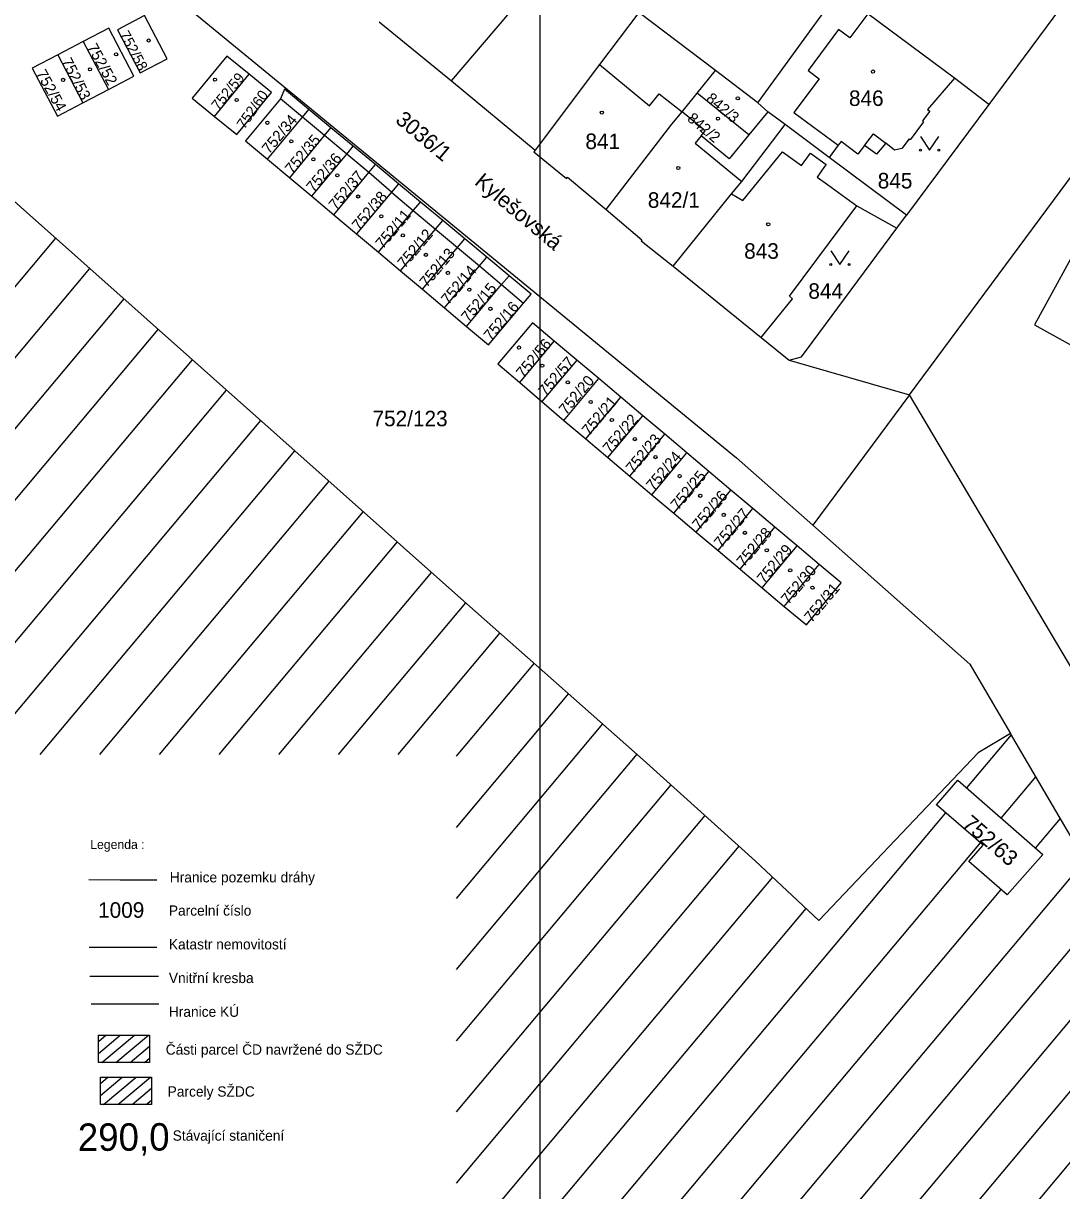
# Model space of a CAD drawing. Extents: x -496682 to -495776, y -1088797 to -1088018.
# Drawn here: x -496193.9 to -496080.3, y -1088434.2 to -1088306.6 of the extents above; entities that cross this region are included whole.
import ezdxf

# ---------------------------------------------------------------- set-up
doc = ezdxf.new("R2010")
doc.units = 0
for name, color, linetype in [('Hranice parcel', 7, 'Continuous'), ('LEGENDA', 7, 'Continuous'), ('Parcelní čísla', 7, 'Continuous'), ('Pop  PČ popisy', 7, 'Continuous'), ('Vnitřní kresba', 7, 'Continuous'), ('Vrstva 20', 7, 'Continuous'), ('Vrstva 63', 7, 'Continuous'), ('Značky budov', 7, 'Continuous'), ('Značky kultur', 7, 'Continuous')]:
    doc.layers.add(name, color=color, linetype=linetype)

msp = doc.modelspace()

# ---------------------------------------------------------------- linework, layer by layer
at = {"layer": 'Hranice parcel'}
for p, q in [((-496113.5, -1088315.25), (-496104.68, -1088303.11)), ((-496079.66, -1088303.84), (-496088.23, -1088315.43)), ((-496118.15, -1088311.73), (-496126.53, -1088305.37)), ((-496154.95, -1088306.41), (-496147.01, -1088312.86)), ((-496187.32, -1088308.54), (-496190.11, -1088310)), ((-496187.32, -1088308.54), (-496184.56, -1088313.8)), ((-496190.11, -1088310), (-496187.36, -1088315.26)), ((-496172.94, -1088316.74), (-496169.17, -1088312.12)), ((-496120.16, -1088314.21), (-496118.15, -1088311.73)), ((-496113.5, -1088315.25), (-496118.15, -1088311.73)), ((-496088.23, -1088315.43), (-496092.02, -1088312.57)), ((-496187.36, -1088315.26), (-496184.56, -1088313.8)), ((-496147.01, -1088312.86), (-496137.88, -1088320.43)), ((-496121.81, -1088316.24), (-496120.16, -1088314.21)), ((-496114.51, -1088318.76), (-496120.16, -1088314.21)), ((-496160.21, -1088317.99), (-496162.63, -1088315.98)), ((-496112.44, -1088316.23), (-496114.51, -1088318.76)), ((-496112.44, -1088316.23), (-496113.5, -1088315.25)), ((-496110.54, -1088317.61), (-496112.44, -1088316.23)), ((-496088.23, -1088315.43), (-496097.26, -1088327.56)), ((-496105.72, -1088321.22), (-496110.54, -1088317.61)), ((-496157.78, -1088320.01), (-496160.21, -1088317.99)), ((-496096.94, -1088347.2), (-496075.94, -1088318.85)), ((-496155.35, -1088322.02), (-496157.78, -1088320.01)), ((-496167.15, -1088321.43), (-496164.73, -1088323.45)), ((-496097.26, -1088327.56), (-496105.72, -1088321.22)), ((-496152.84, -1088324.11), (-496155.35, -1088322.02)), ((-496164.73, -1088323.45), (-496162.32, -1088325.48)), ((-496150.42, -1088326.11), (-496152.84, -1088324.11)), ((-496122.78, -1088333.12), (-496116.38, -1088325.22)), ((-496162.32, -1088325.48), (-496159.9, -1088327.5)), ((-496147.99, -1088328.13), (-496150.42, -1088326.11)), ((-496159.9, -1088327.5), (-496157.42, -1088329.57)), ((-496098.3, -1088328.96), (-496097.26, -1088327.56)), ((-496145.58, -1088330.13), (-496147.99, -1088328.13)), ((-496157.42, -1088329.57), (-496155.02, -1088331.59)), ((-496143.15, -1088332.15), (-496145.58, -1088330.13)), ((-496155.02, -1088331.59), (-496152.6, -1088333.64)), ((-496140.72, -1088334.17), (-496143.15, -1088332.15)), ((-496123.28, -1088332.72), (-496122.78, -1088333.12)), ((-496152.6, -1088333.64), (-496150.21, -1088335.65)), ((-496122.78, -1088333.12), (-496113.14, -1088340.92)), ((-496150.21, -1088335.65), (-496147.79, -1088337.68)), ((-496147.79, -1088337.68), (-496145.37, -1088339.71)), ((-496139.57, -1088345.84), (-496135.78, -1088341.33)), ((-496133.31, -1088343.39), (-496135.78, -1088341.33)), ((-496113.14, -1088340.92), (-496110.08, -1088343.39)), ((-496133.31, -1088343.39), (-496137.13, -1088347.93)), ((-496130.91, -1088345.41), (-496133.31, -1088343.39)), ((-496110.08, -1088343.39), (-496096.94, -1088347.2)), ((-496134.74, -1088349.98), (-496130.91, -1088345.41)), ((-496128.5, -1088347.44), (-496130.91, -1088345.41)), ((-496139.57, -1088345.84), (-496137.13, -1088347.93)), ((-496137.13, -1088347.93), (-496134.74, -1088349.98)), ((-496132.33, -1088352.01), (-496128.5, -1088347.44)), ((-496126.09, -1088349.48), (-496128.5, -1088347.44)), ((-496096.94, -1088347.2), (-496107.5, -1088361.45)), ((-496078.26, -1088378.65), (-496096.94, -1088347.2)), ((-496129.94, -1088354.04), (-496126.09, -1088349.48)), ((-496123.68, -1088351.51), (-496126.09, -1088349.48)), ((-496134.74, -1088349.98), (-496132.33, -1088352.01)), ((-496132.33, -1088352.01), (-496129.94, -1088354.04)), ((-496127.52, -1088356.07), (-496123.68, -1088351.51)), ((-496121.27, -1088353.54), (-496123.68, -1088351.51)), ((-496129.94, -1088354.04), (-496127.52, -1088356.07)), ((-496125.1, -1088358.11), (-496121.27, -1088353.54)), ((-496118.87, -1088355.57), (-496121.27, -1088353.54)), ((-496122.69, -1088360.15), (-496118.87, -1088355.57)), ((-496116.46, -1088357.6), (-496118.87, -1088355.57)), ((-496127.52, -1088356.07), (-496125.1, -1088358.11)), ((-496125.1, -1088358.11), (-496122.69, -1088360.15)), ((-496120.28, -1088362.2), (-496116.46, -1088357.6)), ((-496114.05, -1088359.63), (-496116.46, -1088357.6)), ((-496117.87, -1088364.23), (-496114.05, -1088359.63)), ((-496111.64, -1088361.66), (-496114.05, -1088359.63)), ((-496122.69, -1088360.15), (-496120.28, -1088362.2)), ((-496120.28, -1088362.2), (-496117.87, -1088364.23)), ((-496115.45, -1088366.26), (-496111.64, -1088361.66)), ((-496109.23, -1088363.69), (-496111.64, -1088361.66)), ((-496113.05, -1088368.31), (-496109.23, -1088363.69)), ((-496106.81, -1088365.73), (-496109.23, -1088363.69)), ((-496117.87, -1088364.23), (-496115.45, -1088366.26)), ((-496115.45, -1088366.26), (-496113.05, -1088368.31)), ((-496110.62, -1088370.34), (-496106.81, -1088365.73)), ((-496113.05, -1088368.31), (-496110.62, -1088370.34))]:
    msp.add_line(p, q, dxfattribs=at)
for points in [[(-496188.02, -1088275.91), (-496175.34, -1088305.32), (-496115.85, -1088354.08), (-496107.5, -1088361.45)], [(-496147.01, -1088312.86), (-496138.54, -1088302.87), (-496133.98, -1088296.93)], [(-496092.02, -1088312.57), (-496101.47, -1088305.51), (-496104.68, -1088303.11)], [(-496181.09, -1088311.98), (-496178.12, -1088310.44), (-496180.61, -1088305.71), (-496183.56, -1088307.26), (-496181.09, -1088311.98)], [(-496126.53, -1088305.37), (-496130.83, -1088311.08), (-496137.88, -1088320.43)], [(-496184.56, -1088313.8), (-496181.77, -1088312.35), (-496184.53, -1088307.08), (-496187.32, -1088308.54)], [(-496190.11, -1088310), (-496192.9, -1088311.45), (-496190.14, -1088316.71), (-496187.36, -1088315.26)], [(-496169.17, -1088312.12), (-496171.6, -1088310.15), (-496175.38, -1088314.74), (-496172.94, -1088316.74)], [(-496172.94, -1088316.74), (-496170.5, -1088318.73), (-496166.73, -1088314.13), (-496169.17, -1088312.12)], [(-496092.02, -1088312.57), (-496094.95, -1088315.97), (-496094.7, -1088316.16), (-496095.5, -1088317.24), (-496095.38, -1088317.33), (-496096.85, -1088319.3), (-496096.97, -1088319.21), (-496097.76, -1088320.27), (-496098.57, -1088320.43), (-496099.52, -1088319.68)], [(-496162.63, -1088315.98), (-496165.3, -1088313.76), (-496165.75, -1088314.82), (-496169.56, -1088319.42), (-496167.15, -1088321.43)], [(-496085.86, -1088384.22), (-496089.4, -1088386.33), (-496106.83, -1088404.69), (-496113.8, -1088398.15), (-496126.07, -1088387.1), (-496145.34, -1088370.03), (-496208.08, -1088314.32), (-496232.37, -1088317.97)], [(-496167.15, -1088321.43), (-496163.33, -1088316.82), (-496162.63, -1088315.98)], [(-496130.12, -1088326.92), (-496122.92, -1088317.59), (-496121.81, -1088316.24)], [(-496114.51, -1088318.76), (-496116.67, -1088321.39), (-496119.73, -1088318.87), (-496119.27, -1088318.32), (-496121.81, -1088316.24)], [(-496116.38, -1088325.22), (-496115.28, -1088323.86), (-496110.54, -1088317.61)], [(-496164.73, -1088323.45), (-496160.91, -1088318.84), (-496160.21, -1088317.99)], [(-496162.32, -1088325.48), (-496158.49, -1088320.86), (-496157.78, -1088320.01)], [(-496102.56, -1088320.89), (-496104.41, -1088319.49), (-496104.72, -1088319.89), (-496105.72, -1088321.22)], [(-496099.52, -1088319.68), (-496100.53, -1088320.88), (-496101.83, -1088319.94), (-496102.56, -1088320.89)], [(-496137.88, -1088320.43), (-496138.01, -1088320.62), (-496134.44, -1088323.53), (-496134.33, -1088323.4), (-496130.12, -1088326.92)], [(-496159.9, -1088327.5), (-496156.07, -1088322.89), (-496155.35, -1088322.02)], [(-496152.84, -1088324.11), (-496153.6, -1088325.01), (-496157.42, -1088329.57)], [(-496155.02, -1088331.59), (-496151.21, -1088327.02), (-496150.42, -1088326.11)], [(-496113.14, -1088340.92), (-496109.74, -1088336.7), (-496110.07, -1088336.41), (-496102.69, -1088326.52), (-496098.3, -1088328.96)], [(-496130.12, -1088326.92), (-496126.19, -1088330.23), (-496126.29, -1088330.34), (-496123.28, -1088332.72)], [(-496152.6, -1088333.64), (-496148.78, -1088329.06), (-496147.99, -1088328.13)], [(-496110.08, -1088343.39), (-496108.73, -1088343.04), (-496107.57, -1088341.47), (-496098.3, -1088328.96)], [(-496079.25, -1088341.76), (-496073.47, -1088331.22), (-496077.46, -1088328.98), (-496083.24, -1088339.52), (-496079.25, -1088341.76)], [(-496150.21, -1088335.65), (-496146.38, -1088331.07), (-496145.58, -1088330.13)], [(-496147.79, -1088337.68), (-496143.97, -1088333.1), (-496143.15, -1088332.15)], [(-496145.37, -1088339.71), (-496141.55, -1088335.13), (-496140.72, -1088334.17)], [(-496145.37, -1088339.71), (-496142.97, -1088341.74), (-496139.15, -1088337.15), (-496138.32, -1088336.17), (-496140.72, -1088334.17)], [(-496135.78, -1088341.33), (-496138.17, -1088339.3), (-496141.97, -1088343.81), (-496139.57, -1088345.84)], [(-496107.5, -1088361.45), (-496090.31, -1088376.63), (-496085.86, -1088384.22)], [(-496110.62, -1088370.34), (-496108.2, -1088372.33), (-496104.4, -1088367.76), (-496106.81, -1088365.73)], [(-496000.29, -1088530.17), (-496085.86, -1088384.22)], [(-496088.87, -1088396.45), (-496093.96, -1088392.04), (-496091.62, -1088389.32), (-496082.35, -1088397.47), (-496086.23, -1088401.88), (-496090.44, -1088398.21), (-496088.87, -1088396.45)]]:
    msp.add_lwpolyline(points, dxfattribs=at)
at = {"layer": 'LEGENDA'}
for p, q in [((-496186.68, -1088407.58), (-496179.26, -1088407.58)), ((-496186.6, -1088410.78), (-496179.09, -1088410.78)), ((-496186.46, -1088413.79), (-496179.05, -1088413.79)), ((-496185.65, -1088417.25), (-496185.61, -1088417.22)), ((-496185.65, -1088417.91), (-496184.83, -1088417.22)), ((-496185.65, -1088419.21), (-496183.28, -1088417.22)), ((-496185.29, -1088420.22), (-496181.72, -1088417.22)), ((-496183.74, -1088420.22), (-496180.17, -1088417.22)), ((-496182.18, -1088420.22), (-496180.05, -1088418.43)), ((-496180.63, -1088420.22), (-496180.05, -1088419.74)), ((-496185.44, -1088421.84), (-496185.4, -1088421.8)), ((-496185.44, -1088422.49), (-496184.62, -1088421.8)), ((-496185.44, -1088423.8), (-496183.07, -1088421.8)), ((-496185.08, -1088424.8), (-496181.51, -1088421.8)), ((-496183.53, -1088424.8), (-496179.96, -1088421.8)), ((-496181.97, -1088424.8), (-496179.84, -1088423.01)), ((-496180.42, -1088424.8), (-496179.84, -1088424.32))]:
    msp.add_line(p, q, dxfattribs=at)
msp.add_lwpolyline([(-496186.69, -1088400.21), (-496183.29, -1088400.23), (-496179.28, -1088400.23)], dxfattribs=at)
for points in [[(-496185.65, -1088417.22), (-496180.05, -1088417.22), (-496180.05, -1088420.22), (-496185.65, -1088420.22)], [(-496185.44, -1088421.8), (-496179.84, -1088421.8), (-496179.84, -1088424.8), (-496185.44, -1088424.8)]]:
    msp.add_lwpolyline(points, close=True, dxfattribs=at)
at = {"layer": 'Vnitřní kresba'}
for p, q in [((-496101.47, -1088305.51), (-496103.46, -1088308.16)), ((-496104.69, -1088307.24), (-496108.02, -1088311.73)), ((-496103.46, -1088308.16), (-496104.69, -1088307.24)), ((-496130.83, -1088311.08), (-496125.37, -1088315.57)), ((-496106.81, -1088312.63), (-496109.56, -1088316.31)), ((-496108.02, -1088311.73), (-496106.81, -1088312.63)), ((-496163.33, -1088316.82), (-496165.75, -1088314.82)), ((-496125.37, -1088315.57), (-496124.3, -1088314.26)), ((-496124.3, -1088314.26), (-496121.81, -1088316.24)), ((-496109.56, -1088316.31), (-496104.72, -1088319.89)), ((-496160.91, -1088318.84), (-496163.33, -1088316.82)), ((-496158.49, -1088320.86), (-496160.91, -1088318.84)), ((-496119.73, -1088318.87), (-496120.38, -1088319.67)), ((-496101.83, -1088319.94), (-496100.85, -1088318.64)), ((-496100.85, -1088318.64), (-496099.52, -1088319.68)), ((-496120.38, -1088319.67), (-496115.28, -1088323.86)), ((-496156.07, -1088322.89), (-496158.49, -1088320.86)), ((-496115.16, -1088325.93), (-496110.83, -1088320.6)), ((-496110.83, -1088320.6), (-496108.74, -1088322.12)), ((-496108.74, -1088322.12), (-496107.74, -1088320.75)), ((-496107.74, -1088320.75), (-496106.03, -1088321.99)), ((-496106.21, -1088322.23), (-496107.03, -1088323.37)), ((-496106.03, -1088321.99), (-496106.21, -1088322.23)), ((-496153.6, -1088325.01), (-496156.07, -1088322.89)), ((-496107.03, -1088323.37), (-496105.88, -1088324.2)), ((-496153.6, -1088325.01), (-496151.21, -1088327.02)), ((-496116.38, -1088325.22), (-496115.16, -1088325.93)), ((-496105.88, -1088324.2), (-496102.69, -1088326.52)), ((-496151.21, -1088327.02), (-496148.78, -1088329.06)), ((-496148.78, -1088329.06), (-496146.38, -1088331.07)), ((-496146.38, -1088331.07), (-496143.97, -1088333.1)), ((-496143.97, -1088333.1), (-496141.55, -1088335.13)), ((-496141.55, -1088335.13), (-496139.15, -1088337.15))]:
    msp.add_line(p, q, dxfattribs=at)
at = {"layer": 'Vrstva 20'}
for p, q in [((-496257.84, -1088410.52), (-496190.33, -1088330.06)), ((-496253.85, -1088413.54), (-496186.59, -1088333.38)), ((-496249.85, -1088416.56), (-496182.85, -1088336.7)), ((-496245.86, -1088419.58), (-496179.11, -1088340.03)), ((-496241.87, -1088422.6), (-496175.37, -1088343.35)), ((-496237.88, -1088425.62), (-496171.63, -1088346.67)), ((-496238.03, -1088433.58), (-496167.89, -1088349.99)), ((-496192.02, -1088386.53), (-496164.15, -1088353.31)), ((-496185.49, -1088386.53), (-496160.41, -1088356.63)), ((-496178.96, -1088386.53), (-496156.67, -1088359.95)), ((-496172.44, -1088386.53), (-496152.93, -1088363.27)), ((-496165.91, -1088386.53), (-496149.19, -1088366.59)), ((-496159.38, -1088386.53), (-496145.45, -1088369.92)), ((-496152.86, -1088386.53), (-496141.7, -1088373.23)), ((-496146.49, -1088386.71), (-496137.96, -1088376.55)), ((-496146.49, -1088394.49), (-496134.21, -1088379.87)), ((-496146.49, -1088402.27), (-496130.47, -1088383.18)), ((-496090.64, -1088390.16), (-496085.77, -1088384.36)), ((-496146.49, -1088410.05), (-496126.73, -1088386.5)), ((-496086.88, -1088393.47), (-496083.08, -1088388.94)), ((-496146.49, -1088417.83), (-496123, -1088389.84)), ((-496170.32, -1088485.12), (-496092.94, -1088392.91)), ((-496146.49, -1088425.61), (-496119.29, -1088393.19)), ((-496083.13, -1088396.77), (-496080.4, -1088393.52)), ((-496163.16, -1088484.37), (-496089.16, -1088396.18)), ((-496146.49, -1088433.39), (-496115.57, -1088396.54)), ((-496155.67, -1088491), (-496077.71, -1088398.1)), ((-496146.49, -1088441.17), (-496111.88, -1088399.93)), ((-496159.41, -1088487.68), (-496086.9, -1088401.27)), ((-496151.92, -1088494.31), (-496075.03, -1088402.67)), ((-496174.05, -1088481.79), (-496108.23, -1088403.35)), ((-496148.18, -1088497.63), (-496072.34, -1088407.25)), ((-496144.43, -1088500.94), (-496069.66, -1088411.83)), ((-496140.69, -1088504.26), (-496078.92, -1088430.65))]:
    msp.add_line(p, q, dxfattribs=at)
at = {"layer": 'Vrstva 63'}
msp.add_lwpolyline([(-496137.35, -1088164.24), (-496137.35, -1088461.24), (-496557.35, -1088461.24), (-496557.35, -1088164.24)], close=True, dxfattribs=at)
at = {"layer": 'Značky budov'}
for centre in [(-496180.15, -1088308.44), (-496183.72, -1088309.96), (-496189.52, -1088312.75), (-496186.58, -1088311.59), (-496172.9, -1088312.73), (-496100.92, -1088311.84), (-496170.53, -1088314.95), (-496115.71, -1088314.77), (-496130.58, -1088316.33), (-496167.17, -1088317.44), (-496117.88, -1088316.99), (-496164.55, -1088319.47), (-496162.14, -1088321.43), (-496122.22, -1088322.38), (-496159.52, -1088323.19), (-496157.24, -1088325.5), (-496154.71, -1088327.67), (-496112.38, -1088328.54), (-496152.35, -1088329.75), (-496149.83, -1088331.88), (-496147.42, -1088333.86), (-496145.07, -1088335.69), (-496142.77, -1088337.78), (-496139.65, -1088342.02), (-496137.1, -1088344), (-496134.31, -1088345.83), (-496131.8, -1088347.98), (-496129.48, -1088349.95), (-496126.97, -1088352.03), (-496124.71, -1088354), (-496122.07, -1088356.08), (-496119.82, -1088358.23), (-496117.24, -1088360.32), (-496114.93, -1088362.28), (-496112.54, -1088364.19), (-496109.97, -1088366.39), (-496107.54, -1088368.28)]:
    msp.add_circle(centre, 0.175, dxfattribs=at)
at = {"layer": 'Značky kultur'}
for points in [[(-496095.73, -1088318.94), (-496094.73, -1088320.44), (-496093.73, -1088318.94)], [(-496105.54, -1088331.43), (-496104.54, -1088332.93), (-496103.54, -1088331.43)]]:
    msp.add_lwpolyline(points, dxfattribs=at)
for centre in [(-496095.73, -1088320.44), (-496093.73, -1088320.44), (-496105.54, -1088332.93), (-496103.54, -1088332.93)]:
    msp.add_circle(centre, 0.1, dxfattribs=at)

# ---------------------------------------------------------------- texts
at = {"layer": 'LEGENDA'}
for s, height, rotation, p in [('Legenda :', 1, 359.9999, (-496186.55, -1088396.86)), ('Hranice pozemku dráhy', 1.125, 360, (-496177.85, -1088400.51)), ('Parcelní číslo', 1.125, 360, (-496177.95, -1088404.15)), ('Katastr nemovitostí', 1.125, 360, (-496177.95, -1088407.84)), ('Vnitřní kresba', 1.125, 360, (-496177.95, -1088411.52)), ('Hranice KÚ', 1.125, 360, (-496177.95, -1088415.21)), ('Části parcel ČD navržené do SŽDC ', 1.125, 360, (-496178.29, -1088419.35)), ('Parcely SŽDC', 1.125, 360, (-496178.08, -1088423.94)), ('290,0', 3, 0.2643, (-496187.9, -1088429.88)), ('Stávající staničení', 1.125, 360, (-496177.53, -1088428.76))]:
    msp.add_text(s, height=height, rotation=rotation, dxfattribs=at).set_placement(p)
msp.add_text('1009', height=1.7, dxfattribs=at).set_placement((-496185.69, -1088404.38))
at = {"layer": 'Parcelní čísla'}
for s, height, rotation, p in [('752/58', 1.139, 298, (-496183.39, -1088307.76)), ('752/52', 1.2, 299, (-496186.94, -1088309.17)), ('752/53', 1.2, 297, (-496189.73, -1088310.7)), ('752/54', 1.2, 299, (-496192.51, -1088312.03)), ('752/59', 1.139, 51, (-496172.52, -1088316.17)), ('752/60', 1.139, 55, (-496169.68, -1088318.21)), ('842/3', 1.2, 320, (-496119.27, -1088314.96)), ('3036/1', 1.7, 320, (-496153.27, -1088317.31)), ('842/2', 1.2, 320, (-496121.33, -1088317.13)), ('752/34', 1.2, 50, (-496166.97, -1088320.94)), ('752/35', 1.2, 50, (-496164.44, -1088323.13)), ('752/36', 1.2, 50, (-496162.11, -1088325.13)), ('752/37', 1.2, 50, (-496159.66, -1088327.08)), ('752/38', 1.2, 50, (-496157.12, -1088329.32)), ('752/11', 1.2, 50, (-496154.54, -1088331.31)), ('752/12', 1.2, 50, (-496152.13, -1088333.44)), ('752/13', 1.2, 50, (-496149.72, -1088335.53)), ('752/14', 1.2, 50, (-496147.37, -1088337.41)), ('752/15', 1.2, 50, (-496145.17, -1088339.34)), ('752/16', 1.2, 50, (-496142.71, -1088341.37)), ('752/56', 1.203, 50, (-496139.16, -1088345.45)), ('752/57', 1.213, 49, (-496136.73, -1088347.43)), ('752/20', 1.2, 50, (-496134.48, -1088349.46)), ('752/21', 1.2, 50, (-496131.97, -1088351.73)), ('752/22', 1.2, 50, (-496129.68, -1088353.69)), ('752/23', 1.2, 50, (-496127.16, -1088355.86)), ('752/24', 1.2, 50, (-496124.94, -1088357.76)), ('752/25', 1.2, 50, (-496122.25, -1088359.88)), ('752/26', 1.2, 50, (-496119.9, -1088362.05)), ('752/27', 1.2, 50, (-496117.5, -1088364.01)), ('752/28', 1.2, 50, (-496115.04, -1088366.08)), ('752/29', 1.2, 50, (-496112.81, -1088367.94)), ('752/30', 1.2, 50, (-496110.18, -1088370.2)), ('752/31', 1.2, 50, (-496107.64, -1088372.17)), ('752/63', 1.7, 319, (-496091.26, -1088394.29))]:
    msp.add_text(s, height=height, rotation=rotation, dxfattribs=at).set_placement(p)
for s, p in [('846', (-496103.55, -1088315.6)), ('841', (-496132.38, -1088320.32)), ('845', (-496100.4, -1088324.62)), ('842/1', (-496125.55, -1088326.74)), ('843', (-496115.01, -1088332.31)), ('844', (-496107.99, -1088336.69)), ('752/123', (-496155.67, -1088350.63))]:
    msp.add_text(s, height=1.7, dxfattribs=at).set_placement(p)
at = {"layer": 'Pop  PČ popisy'}
msp.add_text('Kylešovská', height=1.7, rotation=320, dxfattribs=at).set_placement((-496144.61, -1088324.09))

doc.saveas('drawing.dxf')
